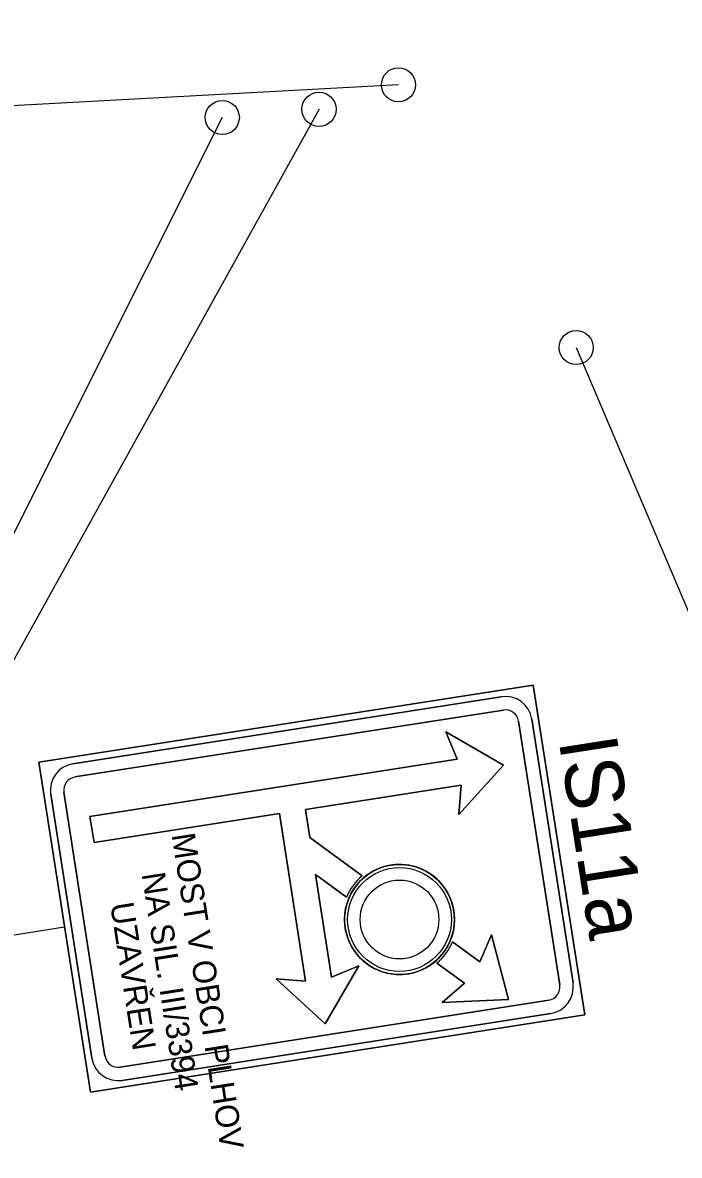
# Model space of a CAD drawing. Extents: x -688893 to -679983, y -1088371 to -1075771.
# Drawn here: x -687501 to -686908, y -1079697 to -1078676 of the extents above; entities that cross this region are included whole.
import ezdxf

# ---------------------------------------------------------------- set-up
doc = ezdxf.new("R2010")
doc.units = 0
for name, color, linetype in [('SDZ', 7, 'Continuous'), ('SDZ ozn', 7, 'Continuous'), ('SDZ plochy', 7, 'Continuous'), ('SDZ symbol', 7, 'Continuous')]:
    doc.layers.add(name, color=color, linetype=linetype)

msp = doc.modelspace()

# ---------------------------------------------------------------- linework, layer by layer
at = {"layer": 'SDZ'}
for p, q in [((-687485.9, -1079342.4), (-687040, -1079272.8)), ((-687040, -1079272.8), (-686993.5, -1079570.1)), ((-687455.2, -1079343.7), (-687068.8, -1079283.4)), ((-687453.4, -1079355.6), (-687066.9, -1079295.3)), ((-687053.2, -1079305.3), (-687016, -1079543.1)), ((-687041.3, -1079303.4), (-687004.1, -1079541.3)), ((-687439.5, -1079639.7), (-687485.9, -1079342.4)), ((-687438.2, -1079609.1), (-687475.3, -1079371.2)), ((-687426.3, -1079607.2), (-687463.4, -1079369.4)), ((-687462.7, -1079491.1), (-687551.6, -1079505)), ((-687026, -1079556.9), (-687412.5, -1079617.2)), ((-686993.5, -1079570.1), (-687439.5, -1079639.7)), ((-687024.2, -1079568.8), (-687410.7, -1079629.1))]:
    msp.add_line(p, q, dxfattribs=at)
for points in [[(-687161.6, -1078731.6), (-688008.9, -1078777.5), (-688094.4, -1078474.4)], [(-687233.2, -1078753.7), (-687560.7, -1079343.2), (-687551.6, -1079505)], [(-687320.5, -1078761.1), (-687804.8, -1079726.1), (-687758.7, -1079941.2)], [(-687001.2, -1078968.5), (-686694.8, -1079689.1), (-686491.3, -1079678.6)]]:
    msp.add_lwpolyline(points, dxfattribs=at)
for centre, radius in [((-687161.6, -1078731.6), 15.4), ((-687233.2, -1078753.7), 15.4), ((-687320.5, -1078761.1), 15.4), ((-687001.2, -1078968.5), 15.4), ((-687160.6, -1079484.1), 46.8), ((-687160.6, -1079484.1), 35.5)]:
    msp.add_circle(centre, radius, dxfattribs=at)
for centre, radius, start, end in [((-687065.1, -1079307.1), 24.1, 8.8784, 98.8784), ((-687065.1, -1079307.1), 12, 8.8784, 98.8784), ((-687451.5, -1079367.5), 24.1, 98.8784, 188.8784), ((-687451.5, -1079367.5), 12, 98.8784, 188.8784), ((-687160.6, -1079484.1), 49.6, 310.0276, 157.7291), ((-687027.9, -1079545), 12, 278.8784, 8.8784), ((-687027.9, -1079545), 24.1, 278.8784, 8.8784), ((-687414.4, -1079605.3), 24.1, 188.8784, 278.8784), ((-687414.4, -1079605.3), 12, 188.8784, 278.8784)]:
    msp.add_arc(centre, radius, start, end, dxfattribs=at)
at = {"layer": 'SDZ plochy'}
for p, q in [((-687040, -1079272.8), (-687485.9, -1079342.4)), ((-687040, -1079272.8), (-687485.9, -1079342.4)), ((-686993.5, -1079570.1), (-687040, -1079272.8)), ((-686993.5, -1079570.1), (-687040, -1079272.8)), ((-687068.8, -1079283.4), (-687455.2, -1079343.7)), ((-687455.2, -1079343.7), (-687068.8, -1079283.4)), ((-687455.2, -1079343.7), (-687068.8, -1079283.4)), ((-687453.4, -1079355.6), (-687066.9, -1079295.3)), ((-687066.9, -1079295.3), (-687453.4, -1079355.6)), ((-687053.2, -1079305.3), (-687016, -1079543.1)), ((-687016, -1079543.1), (-687053.2, -1079305.3)), ((-687004.1, -1079541.3), (-687041.3, -1079303.4)), ((-687041.3, -1079303.4), (-687004.1, -1079541.3)), ((-687041.3, -1079303.4), (-687004.1, -1079541.3)), ((-687066.7, -1079345.1), (-687118.7, -1079314.8)), ((-687118.7, -1079314.8), (-687108.7, -1079339.5)), ((-687108.7, -1079339.5), (-687118.7, -1079314.8)), ((-687118.7, -1079314.8), (-687066.7, -1079345.1)), ((-687485.9, -1079342.4), (-687439.5, -1079639.7)), ((-687485.9, -1079342.4), (-687439.5, -1079639.7)), ((-687108.7, -1079339.5), (-687439.9, -1079391.2)), ((-687439.9, -1079391.2), (-687108.7, -1079339.5)), ((-687107, -1079389.4), (-687066.7, -1079345.1)), ((-687066.7, -1079345.1), (-687107, -1079389.4)), ((-687245.5, -1079384.9), (-687105.1, -1079362.9)), ((-687105.1, -1079362.9), (-687245.5, -1079384.9)), ((-687105.1, -1079362.9), (-687107, -1079389.4)), ((-687107, -1079389.4), (-687105.1, -1079362.9)), ((-687475.3, -1079371.2), (-687438.2, -1079609.1)), ((-687438.2, -1079609.1), (-687475.3, -1079371.2)), ((-687438.2, -1079609.1), (-687475.3, -1079371.2)), ((-687426.3, -1079607.2), (-687463.4, -1079369.4)), ((-687463.4, -1079369.4), (-687426.3, -1079607.2)), ((-687241.6, -1079410.3), (-687245.5, -1079384.9)), ((-687245.5, -1079384.9), (-687241.6, -1079410.3)), ((-687439.9, -1079391.2), (-687436.2, -1079414.7)), ((-687436.2, -1079414.7), (-687439.9, -1079391.2)), ((-687436.2, -1079414.7), (-687269, -1079388.6)), ((-687269, -1079388.6), (-687436.2, -1079414.7)), ((-687269, -1079388.6), (-687245.4, -1079539.6)), ((-687245.4, -1079539.6), (-687269, -1079388.6)), ((-687194.4, -1079444.7), (-687241.6, -1079410.3)), ((-687241.6, -1079410.3), (-687194.4, -1079444.7)), ((-687221.9, -1079536), (-687236.4, -1079443.5)), ((-687236.4, -1079443.5), (-687208.4, -1079463.9)), ((-687208.4, -1079463.9), (-687236.4, -1079443.5)), ((-687236.4, -1079443.5), (-687221.9, -1079536)), ((-687077.6, -1079497.9), (-687088, -1079522.4)), ((-687088, -1079522.4), (-687077.6, -1079497.9)), ((-687062.2, -1079556.1), (-687077.6, -1079497.9)), ((-687077.6, -1079497.9), (-687062.2, -1079556.1)), ((-687088, -1079522.4), (-687112.8, -1079504.3)), ((-687112.8, -1079504.3), (-687088, -1079522.4)), ((-687227.6, -1079578), (-687197.3, -1079526)), ((-687197.3, -1079526), (-687227.6, -1079578)), ((-687197.3, -1079526), (-687221.9, -1079536)), ((-687221.9, -1079536), (-687197.3, -1079526)), ((-687126.8, -1079523.5), (-687102, -1079541.6)), ((-687102, -1079541.6), (-687126.8, -1079523.5)), ((-687245.4, -1079539.6), (-687271.9, -1079537.7)), ((-687271.9, -1079537.7), (-687227.6, -1079578)), ((-687227.6, -1079578), (-687271.9, -1079537.7)), ((-687271.9, -1079537.7), (-687245.4, -1079539.6)), ((-687102, -1079541.6), (-687122.1, -1079559)), ((-687122.1, -1079559), (-687102, -1079541.6)), ((-687026, -1079556.9), (-687412.5, -1079617.2)), ((-687412.5, -1079617.2), (-687026, -1079556.9)), ((-687122.1, -1079559), (-687062.2, -1079556.1)), ((-687062.2, -1079556.1), (-687122.1, -1079559)), ((-687439.5, -1079639.7), (-686993.5, -1079570.1)), ((-687439.5, -1079639.7), (-686993.5, -1079570.1)), ((-687410.7, -1079629.1), (-687024.2, -1079568.8)), ((-687024.2, -1079568.8), (-687410.7, -1079629.1)), ((-687024.2, -1079568.8), (-687410.7, -1079629.1))]:
    msp.add_line(p, q, dxfattribs=at)
for radius in [46.8, 46.8, 35.5, 35.5]:
    msp.add_circle((-687160.6, -1079484.1), radius, dxfattribs=at)
for centre, radius, start, end in [((-687065.1, -1079307.1), 24.1, 8.8784, 98.8784), ((-687065.1, -1079307.1), 24.1, 8.8784, 98.8784), ((-687065.1, -1079307.1), 24.1, 8.8784, 98.8784), ((-687065.1, -1079307.1), 12, 8.8784, 98.8784), ((-687065.1, -1079307.1), 12, 8.8784, 98.8784), ((-687451.5, -1079367.5), 24.1, 98.8784, 188.8784), ((-687451.5, -1079367.5), 24.1, 98.8784, 188.8784), ((-687451.5, -1079367.5), 24.1, 98.8784, 188.8784), ((-687451.5, -1079367.5), 12, 98.8784, 188.8784), ((-687451.5, -1079367.5), 12, 98.8784, 188.8784), ((-687160.6, -1079484.1), 49.6, 157.7291, 98.8784), ((-687160.6, -1079484.1), 49.6, 98.8784, 278.8784), ((-687160.6, -1079484.1), 49.6, 98.8784, 157.7291), ((-687160.6, -1079484.1), 49.6, 278.8784, 98.8784), ((-687160.6, -1079484.1), 51.9, 130.6463, 157.1104), ((-687160.6, -1079484.1), 51.9, 130.6463, 157.1104), ((-687160.6, -1079484.1), 51.9, 310.6463, 337.1104), ((-687160.6, -1079484.1), 51.9, 310.6463, 337.1104), ((-687027.9, -1079545), 12, 278.8784, 8.8784), ((-687027.9, -1079545), 12, 278.8784, 8.8784), ((-687027.9, -1079545), 24.1, 278.8784, 8.8784), ((-687027.9, -1079545), 24.1, 278.8784, 8.8784), ((-687027.9, -1079545), 24.1, 278.8784, 8.8784), ((-687414.4, -1079605.3), 24.1, 188.8784, 278.8784), ((-687414.4, -1079605.3), 24.1, 188.8784, 278.8784), ((-687414.4, -1079605.3), 24.1, 188.8784, 278.8784), ((-687414.4, -1079605.3), 12, 188.8784, 278.8784), ((-687414.4, -1079605.3), 12, 188.8784, 278.8784)]:
    msp.add_arc(centre, radius, start, end, dxfattribs=at)
at = {"layer": 'SDZ symbol'}
for p, q in [((-687108.7, -1079339.5), (-687118.7, -1079314.8)), ((-687118.7, -1079314.8), (-687066.7, -1079345.1)), ((-687439.9, -1079391.2), (-687108.7, -1079339.5)), ((-687066.7, -1079345.1), (-687107, -1079389.4)), ((-687105.1, -1079362.9), (-687245.5, -1079384.9)), ((-687107, -1079389.4), (-687105.1, -1079362.9)), ((-687245.5, -1079384.9), (-687241.6, -1079410.3)), ((-687436.2, -1079414.7), (-687439.9, -1079391.2)), ((-687269, -1079388.6), (-687436.2, -1079414.7)), ((-687269, -1079388.6), (-687245.4, -1079539.6)), ((-687241.6, -1079410.3), (-687194.4, -1079444.7)), ((-687236.4, -1079443.5), (-687208.4, -1079463.9)), ((-687236.4, -1079443.5), (-687221.9, -1079536)), ((-687088, -1079522.4), (-687077.6, -1079497.9)), ((-687077.6, -1079497.9), (-687062.2, -1079556.1)), ((-687112.8, -1079504.3), (-687088, -1079522.4)), ((-687197.3, -1079526), (-687227.6, -1079578)), ((-687221.9, -1079536), (-687197.3, -1079526)), ((-687126.8, -1079523.5), (-687102, -1079541.6)), ((-687227.6, -1079578), (-687271.9, -1079537.7)), ((-687271.9, -1079537.7), (-687245.4, -1079539.6)), ((-687122.1, -1079559), (-687102, -1079541.6)), ((-687062.2, -1079556.1), (-687122.1, -1079559))]:
    msp.add_line(p, q, dxfattribs=at)
msp.add_circle((-687160.6, -1079484.1), 49.6, dxfattribs=at)
for start, end in [(130.6463, 157.1104), (310.6463, 337.1104)]:
    msp.add_arc((-687160.6, -1079484.1), 51.9, start, end, dxfattribs=at)

# ---------------------------------------------------------------- texts
at = {"layer": 'SDZ ozn'}
msp.add_text('IS11a', height=52.5, rotation=278.8784, dxfattribs=at).set_placement((-687017.1, -1079322.7))
at = {"layer": 'SDZ symbol'}
for s, height, p in [('MOST V OBCI PLHOV', 21.084, (-687366.3, -1079407.7)), ('NA SIL. III/3394', 21.084, (-687393.3, -1079443.1)), ('UZAVŘEN', 21.08, (-687421.7, -1079470.2))]:
    msp.add_text(s, height=height, rotation=278.8784, dxfattribs=at).set_placement(p)

doc.saveas('drawing.dxf')
